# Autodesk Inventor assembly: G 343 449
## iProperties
Company: Mayer & Müller AG
Created: 2006-04
Part Number: G 343 449
Document SubType Name: Weldment
Designer: I.Baliuc
Description: Abdeckung, links
Material: Geschweißt
Mass: 144.878 g
Surface Area: 148.743 cm^2
Volume: 18.4793 cm^3
Density: 7.84 g/cm^3
Zweck: LBK DC - Schalter
Author: T.Messerschmitt
Revision Number: 343449
